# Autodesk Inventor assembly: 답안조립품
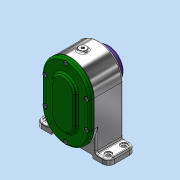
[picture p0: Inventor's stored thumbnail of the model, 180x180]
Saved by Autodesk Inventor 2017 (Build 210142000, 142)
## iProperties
Part Number: 답안조립품
Material: 일반
Document SubType Name: Assembly
Designer: MRC
Author: MRC
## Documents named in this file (19)
- C:\Users\MRC\Desktop\710609V1007\답안조립품.iam
- C:\Users\MRC\Desktop\710609V1007\본체.ipt
- C:\Users\MRC\Desktop\710609V1007\개스킷 A.ipt
- C:\Users\MRC\Desktop\710609V1007\개스킷 B.ipt
- C:\Users\MRC\Desktop\710609V1007\베어링 6001.ipt
- 베어링 6001.ipt
- C:\Users\MRC\Desktop\710609V1007\베어링 6002.ipt
- 베어링 6002.ipt
- C:\Users\MRC\Desktop\710609V1007\볼트 M4.ipt
- C:\Users\MRC\Desktop\710609V1007\스퍼기어 A.ipt
- C:\Users\MRC\Desktop\710609V1007\스퍼기어 B.ipt
- C:\Users\MRC\Desktop\710609V1007\오일 실 12 22 7.ipt
- C:\Users\MRC\Desktop\710609V1007\축 A.ipt
- C:\Users\MRC\Desktop\710609V1007\축 B.ipt
- C:\Users\MRC\Desktop\710609V1007\칼라.ipt
- C:\Users\MRC\Desktop\710609V1007\커버 A.ipt
- C:\Users\MRC\Desktop\710609V1007\커버 B.ipt
- C:\Users\MRC\Desktop\710609V1007\키 4 x 4 x 12.ipt
- C:\Users\MRC\Desktop\710609V1007\키 5 x 5 x 12.ipt
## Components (2 placed, 2 different names)
1. 개스킷 A:1
2. 개스킷 B:1
